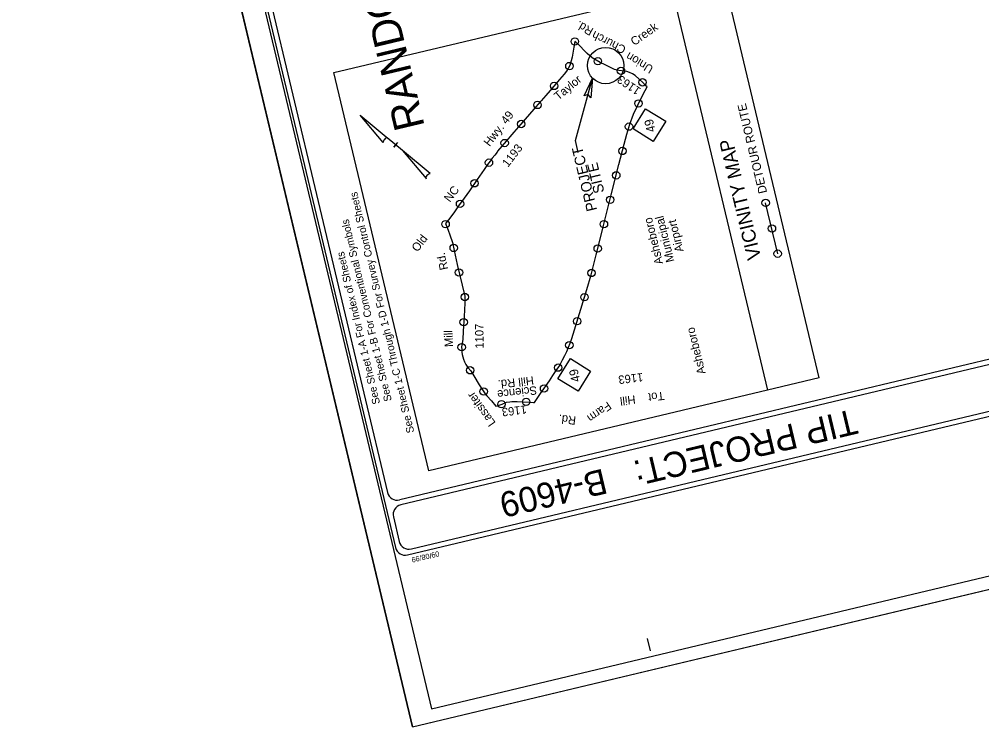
# Model space of a CAD drawing. Extents: x 1734738 to 1742883, y 698103 to 703125.
# Drawn here: x 1734738 to 1736650, y 698103 to 699508 of the extents above; entities that cross this region are included whole.
import ezdxf

# ---------------------------------------------------------------- set-up
doc = ezdxf.new("R2010")
doc.units = 0
for name, color, linetype in [('Exist Map Preparation Border Sheet 1 CELL', 7, 'Continuous'), ('Exist Road Primary US Structure Cantilever Sign Number Label', 7, 'Continuous'), ('Exist Road Primary US Structure Standard Bridge Number Label', 7, 'Continuous'), ('Exist Road Secondary Structure Culvert Number Label', 7, 'Continuous'), ('Exist Road Secondary Structure Pipe Number Label', 7, 'Continuous'), ('Exist Road Secondary Type 41 Number Label', 7, 'Continuous'), ('Exist Road Secondary Type 41 SR Number Label', 7, 'Continuous'), ('Exist Road Secondary Type 51 Divided Label', 7, 'Continuous'), ('Level 53', 7, 'Continuous')]:
    doc.layers.add(name, color=color, linetype=linetype)

msp = doc.modelspace()

# ---------------------------------------------------------------- linework, layer by layer
at = {"layer": 'Exist Road Primary US Structure Cantilever Sign Number Label'}
for p, q in [((1735415.2, 699317.4), (1735415.2, 699317.4)), ((1735415.2, 699317.4), (1735415.2, 699317.4)), ((1735460.9, 699262.7), (1735415.2, 699317.4)), ((1735415.2, 699317.4), (1735470.6, 699270.9)), ((1735499.4, 699246.7), (1735469, 699272.3)), ((1735470.6, 699270.9), (1735469.1, 699272.2)), ((1735485.5, 699257.5), (1735482, 699253.4)), ((1735482, 699253.4), (1735482, 699253.3)), ((1735482.1, 699253.5), (1735489.9, 699262.7)), ((1735499.4, 699246.7), (1735546, 699191.1)), ((1735553.9, 699201), (1735499.4, 699246.7)), ((1735670.9, 699222.8), (1735670.9, 699222.8)), ((1736244.7, 699042.1), (1736220.4, 699143.3))]:
    msp.add_line(p, q, dxfattribs=at)
for points in [[(1735841.5, 699463.4), (1735839.5, 699452.1), (1735836.1, 699432.1), (1735834.4, 699424.9), (1735832.9, 699420.3), (1735831.4, 699416.1), (1735828.4, 699410.1), (1735825, 699404.6), (1735820.4, 699398.5), (1735811.2, 699388), (1735792.6, 699366), (1735784, 699356.1), (1735774.4, 699345.5), (1735772.8, 699343.6)], [(1735901.7, 699416.8), (1735892, 699421.6), (1735876, 699431), (1735866.2, 699439.9), (1735862.5, 699443.2), (1735849.2, 699456.6), (1735843.7, 699462), (1735841.5, 699463.4)], [(1735985.2, 699373.3), (1735982.5, 699375.4), (1735976.4, 699381.9), (1735969.5, 699388.7), (1735961.5, 699396), (1735956.1, 699399.2), (1735950, 699402), (1735944.5, 699403.8), (1735939.9, 699404.5), (1735929.1, 699405.6), (1735920.1, 699408.1), (1735901.7, 699416.8)], [(1735944.5, 699279.2), (1735950.5, 699299), (1735958, 699319.1), (1735966.4, 699337.1), (1735977.5, 699358.9), (1735985.2, 699373.3)], [(1735772.8, 699343.6), (1735759.9, 699328.9), (1735734.4, 699299), (1735720.5, 699283.2), (1735701.1, 699260.6), (1735688.2, 699245.5), (1735686.9, 699243.9)], [(1735892.3, 699073.7), (1735898.7, 699098.3), (1735907.1, 699132.6), (1735913.9, 699158.7), (1735929.2, 699219.2), (1735939.5, 699259.7), (1735944.5, 699279.2)], [(1735686.9, 699243.9), (1735682.4, 699237.9), (1735677.6, 699231.8), (1735673.9, 699226.8)], [(1735673.9, 699226.8), (1735670.2, 699221.8), (1735661.3, 699209), (1735647.2, 699189.2), (1735632.2, 699167.2), (1735621.4, 699152.4), (1735610.7, 699136.8), (1735602.4, 699125.4), (1735592.9, 699112.8), (1735584.3, 699101.8)], [(1735584.3, 699101.8), (1735590, 699088.8), (1735593.5, 699079.7), (1735598.3, 699064.1), (1735602, 699048.7), (1735607.8, 699020.5), (1735612.1, 699001.5), (1735617.7, 698979.5), (1735622.8, 698957.6)], [(1735761.4, 698746.6), (1735763.8, 698750.2), (1735773.6, 698764.5), (1735791, 698789.9), (1735797.8, 698800), (1735804.6, 698810.1), (1735809.4, 698817.6), (1735812.8, 698823.5), (1735817.1, 698831), (1735821.6, 698839.8), (1735825.4, 698848), (1735829.2, 698856.7), (1735832.2, 698864.3), (1735835.6, 698873.5), (1735850.9, 698923.4), (1735860.5, 698955.9), (1735865.2, 698971.2), (1735873.6, 699000.4), (1735883.8, 699040), (1735892.3, 699073.7)], [(1735622.8, 698957.6), (1735623.3, 698952.8), (1735622.9, 698943.6), (1735621.4, 698917.5), (1735619.7, 698888.3), (1735618.9, 698871.9), (1735616.6, 698857), (1735616.9, 698851), (1735617.1, 698846.2), (1735618, 698841.8), (1735618.8, 698837.2), (1735620.6, 698832.3), (1735622.4, 698827.5), (1735624.8, 698822.3), (1735629.2, 698816), (1735634.6, 698809.2), (1735641.2, 698799.4), (1735651.6, 698781.9), (1735663.5, 698763.6), (1735666.9, 698759.8), (1735676, 698750.1), (1735684.6, 698739.1)], [(1735684.6, 698739.1), (1735687.3, 698740), (1735696.9, 698743.4), (1735706, 698747.1), (1735712.2, 698748.2), (1735716.5, 698748.5), (1735727, 698748.3), (1735738.6, 698748), (1735753.2, 698747.5), (1735759.1, 698746.8), (1735761.4, 698746.6)]]:
    msp.add_lwpolyline(points, dxfattribs=at)
for centre, start_param, end_param in [((1735465.5, 699267.1), 0.216388, 2.908219), ((1735550.3, 699195.8), 0.201328, 3.141593)]:
    msp.add_ellipse(centre, major_axis=(4.15, 4.87), ratio=0.461098, start_param=start_param, end_param=end_param, dxfattribs=at)
at = {"layer": 'Exist Road Primary US Structure Standard Bridge Number Label'}
for q in [(1734738, 701378.8), (1737658.8, 698612.7)]:
    msp.add_line((1735518.8, 698102.6), q, dxfattribs=at)
at = {"layer": 'Exist Road Secondary Structure Culvert Number Label'}
for p, q in [((1736326.6, 698795.4), (1736138, 699586.7)), ((1735842.5, 699266.7), (1735876.7, 699390.6)), ((1735848, 699243.3), (1735842.5, 699266.7)), ((1736326.6, 698795.4), (1736224.2, 698771))]:
    msp.add_line(p, q, dxfattribs=at)
msp.add_lwpolyline([(1735551.6, 698610.7), (1735363, 699402), (1736035.6, 699562.3), (1736224.2, 698771)], close=True, dxfattribs=at)
for centre, radius in [((1735841.5, 699463.4), 7.34), ((1735902.6, 699415.7), 36.1), ((1735830.7, 699414.7), 7.34), ((1735887.3, 699424.3), 7.34), ((1735933.1, 699405.2), 7.34), ((1735975.9, 699382.4), 7.34), ((1735800.3, 699375.2), 7.34), ((1735968.1, 699340.5), 7.34), ((1735767.5, 699337.5), 7.34), ((1735734.9, 699299.6), 7.34), ((1735949.1, 699294.4), 7.34), ((1735702.1, 699261.8), 7.34), ((1735936, 699246.1), 7.34), ((1735670.9, 699222.8), 7.34), ((1735923.8, 699197.6), 7.34), ((1735642.2, 699181.9), 7.34), ((1735911.5, 699149.2), 7.34), ((1735613.5, 699140.9), 7.34), ((1736220.5, 699142.9), 7.34), ((1735584.8, 699100.7), 7.34), ((1735899.3, 699100.7), 7.34), ((1736233, 699092), 7.34), ((1735600.9, 699053.5), 7.34), ((1735886.9, 699052.2), 7.34), ((1736244.4, 699042.1), 7.34), ((1735611.4, 699004.6), 7.34), ((1735874.5, 699003.8), 7.34), ((1735623, 698956), 7.34), ((1735860.5, 698955.8), 7.34), ((1735620.7, 698906.1), 7.34), ((1735846.1, 698907.9), 7.34), ((1735830.6, 698860.4), 7.34), ((1735616.7, 698856.3), 7.34), ((1735633.5, 698810.5), 7.34), ((1735808.3, 698815.8), 7.34), ((1735660.4, 698768.3), 7.34), ((1735780.3, 698774.3), 7.34), ((1735745, 698747.8), 7.34), ((1735695.9, 698743.1), 7.34)]:
    msp.add_circle(centre, radius, dxfattribs=at)
at = {"layer": 'Exist Road Secondary Structure Pipe Number Label'}
msp.add_lwpolyline([(1737609.2, 698627.6), (1736836.4, 701869.7), (1734783.7, 701380.5), (1735556.5, 698138.3)], close=True, dxfattribs=at)
at = {"layer": 'Exist Road Secondary Type 41 Number Label'}
msp.add_lwpolyline([(1735860.2, 699355.6), (1735876.7, 699390.6), (1735873, 699351.8), (1735867.8, 699358.3)], close=True, dxfattribs=at)
at = {"layer": 'Exist Road Secondary Type 41 SR Number Label'}
msp.add_lwpolyline([(1734738, 701378.8), (1735518.8, 698102.6), (1737658.8, 698612.7), (1736878, 701888.9)], close=True, dxfattribs=at)
at = {"layer": 'Exist Road Secondary Type 51 Divided Label'}
for p, q in [((1737480.4, 699016.3), (1735496, 698543.3)), ((1737118.2, 698940.2), (1735493.7, 698553.1)), ((1735991.8, 698253.4), (1735986, 698277.7)), ((1735991.8, 698253.4), (1735986, 698277.7))]:
    msp.add_line(p, q, dxfattribs=at)
for points in [[(1734799.1, 701337.9), (1735485.4, 698458.5)], [(1734811.2, 701330.5), (1735469.6, 698567.9)], [(1735516.9, 698455.8), (1737501.3, 698928.8)], [(1735509.4, 698443.7), (1737513.3, 698921.3)], [(1735509.4, 698443.7), (1737513.3, 698921.3)], [(1735481.2, 698519.2), (1735492.8, 698470.6)]]:
    msp.add_lwpolyline(points, dxfattribs=at)
for centre, start, end in [((1735488.9, 698572.5), 193.4059, 283.4059), ((1735500.5, 698523.9), 103.4059, 193.4059), ((1735512.1, 698475.2), 193.4059, 283.4059), ((1735504.7, 698463.2), 193.4059, 283.4059)]:
    msp.add_arc(centre, 20, start, end, dxfattribs=at)
at = {"layer": 'Level 53'}
for p, q in [((1735957.4, 699290), (1735982.1, 699330)), ((1735982.1, 699330), (1736022.2, 699305.2)), ((1735997.4, 699265.2), (1735957.4, 699290)), ((1736022.2, 699305.2), (1735997.4, 699265.2)), ((1735808, 698793.8), (1735832.8, 698833.9)), ((1735832.8, 698833.9), (1735872.8, 698809.1)), ((1735848.1, 698769), (1735808, 698793.8)), ((1735872.8, 698809.1), (1735848.1, 698769))]:
    msp.add_line(p, q, dxfattribs=at)

# ---------------------------------------------------------------- texts
at = {"layer": 'Exist Map Preparation Border Sheet 1 CELL'}
msp.add_text('       RANDOLPH COUNTY       ', height=60, rotation=103.4059, dxfattribs=at).set_placement((1735579.7, 699143.2))
at = {"layer": 'Exist Road Primary US Structure Cantilever Sign Number Label'}
msp.add_text('DETOUR ROUTE', height=17.126, rotation=103.4765, dxfattribs=at).set_placement((1736223.6, 699163.7))
at = {"layer": 'Exist Road Secondary Structure Culvert Number Label'}
for s, height, p in [('PROJECT', 20.93, (1735886, 699129)), ('VICINITY MAP', 27.523, (1736211.6, 699033.5)), ('SITE', 20.93, (1735900.3, 699164.5))]:
    msp.add_text(s, height=height, rotation=103.4062, dxfattribs=at).set_placement(p)
at = {"layer": 'Exist Road Secondary Type 51 Divided Label'}
for s, height, rotation, p in [('See Sheet 1-C Through 1-D For Survey Control Sheets', 15, 103.4059, (1735522.6, 698687.8)), ('See Sheet 1-B For Conventional Symbols', 15, 103.4059, (1735478, 698750.4)), ('See Sheet 1-A For Index of Sheets', 15, 103.4059, (1735454.8, 698744.8)), ('TIP PROJECT:', 50, 193.4059, (1736395.3, 698734.3)), ('B-4609  ', 50, 193.4059, (1735898.1, 698615.7)), ('09/08/99', 10.5, 193.4059, (1735571, 698451.7))]:
    msp.add_text(s, height=height, rotation=rotation, dxfattribs=at).set_placement(p)
at = {"layer": 'Level 53'}
for s, height, rotation, p in [('Rd.', 16.65, 150.4117, (1735880, 699488.5)), ('Creek', 16.65, 35.0776, (1735959.6, 699454.3)), ('Church', 16.65, 153.2779, (1735944.7, 699452.7)), ('Union', 16.65, 148.7381, (1735999.1, 699413)), ('Taylor', 16.65, 39.786, (1735808.9, 699345.8)), ('1163', 16.65, 145.7675, (1735974, 699369.5)), ('Hwy. 49', 16.65, 52.3823, (1735672.1, 699253.8)), ('49', 17.5, 103.2681, (1736001.9, 699285.5)), ('1193', 16.65, 52.3823, (1735708.6, 699212.6)), ('NC', 16.65, 52.3823, (1735593.2, 699143.1)), ('Municipal', 16.65, 103.8062, (1736039.3, 699027.2)), ('Asheboro', 16.65, 103.8062, (1736017, 699022.9)), ('Airport', 16.65, 103.8062, (1736057.6, 699047.5)), ('Old', 16.65, 52.3823, (1735528.9, 699044.4)), ('Rd.', 16.65, 101.9992, (1735590, 699011.5)), ('Mill', 16.65, 92.131, (1735599.6, 698857)), ('1107', 16.65, 90.7446, (1735660.4, 698853.7)), ('Asheboro', 16.65, 103.8062, (1736101.4, 698804.8)), ('49', 17.5, 103.2681, (1735852.5, 698789.3)), ('Hill Rd.', 16.65, 186.5223, (1735759, 698798.7)), ('1163', 16.65, 186.5223, (1735976.4, 698805.2)), ('Science', 16.65, 186.5223, (1735765.2, 698779.3)), ('Lassiter', 16.65, 125.3894, (1735685, 698706.2)), ('Hill', 16.65, 186.5223, (1735961, 698760.8)), ('Tot', 16.65, 186.5223, (1736018.3, 698768.4)), ('1163', 16.65, 186.5223, (1735745, 698741)), ('Farm', 16.65, 214.7147, (1735906.7, 698749.1)), ('Rd.', 16.65, 173.3965, (1735844.6, 698718.6))]:
    msp.add_text(s, height=height, rotation=rotation, dxfattribs=at).set_placement(p)

doc.saveas('drawing.dxf')
